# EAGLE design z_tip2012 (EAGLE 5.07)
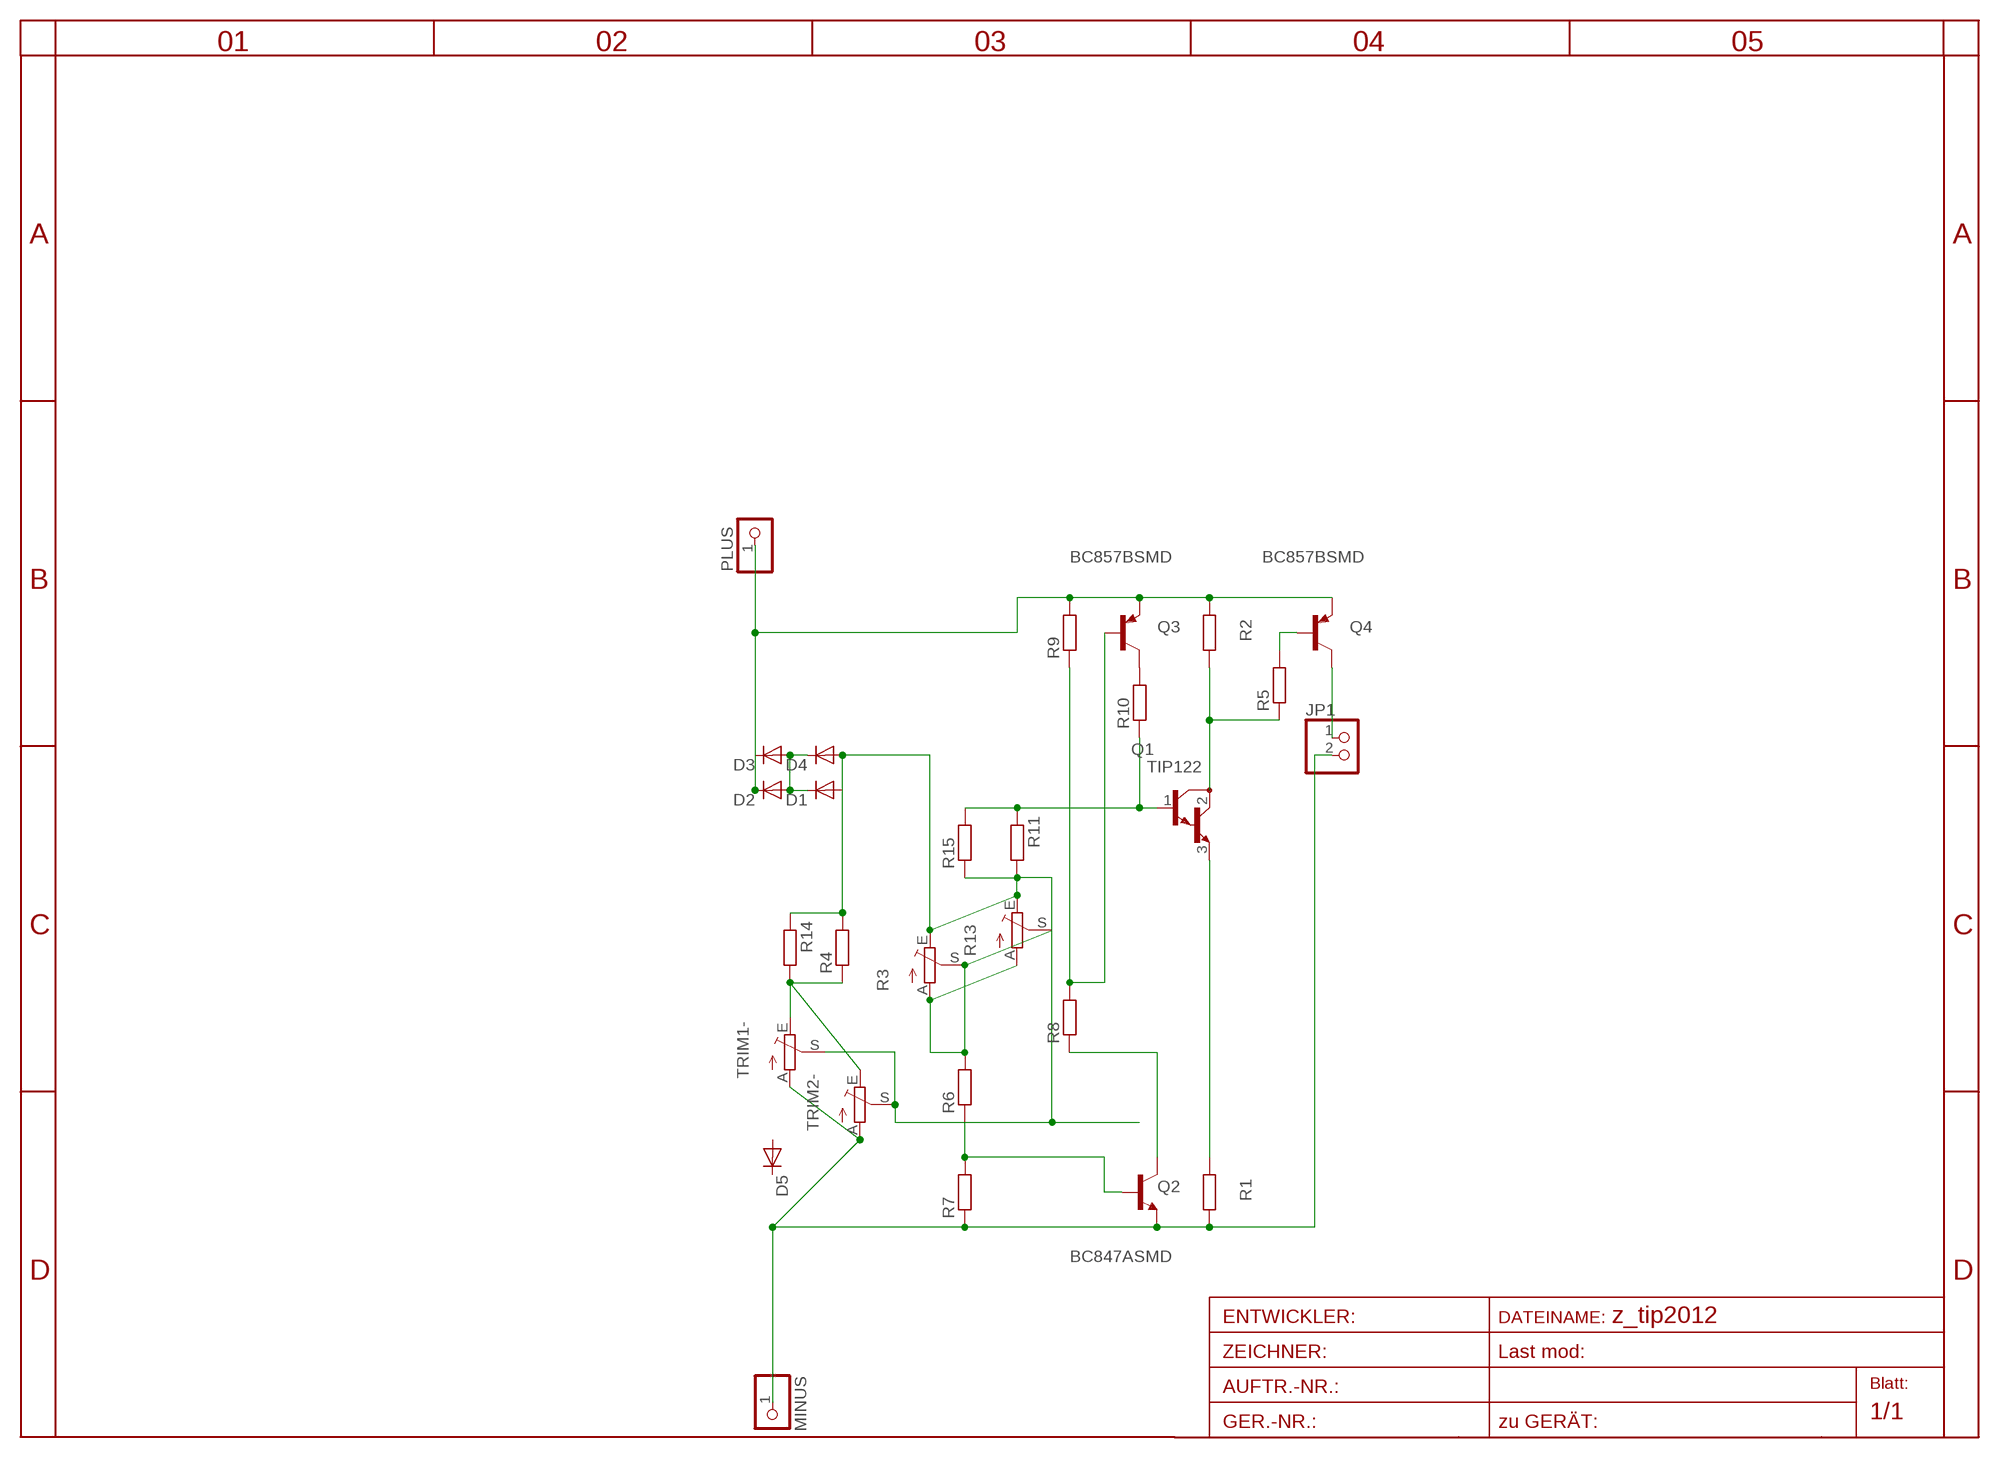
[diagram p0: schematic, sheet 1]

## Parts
D1  DIODE-MINIMELF  [MINIMELF]
D2  DIODE-MINIMELF  [MINIMELF]
D3  DIODE-D-2.5  [D-2.5]
D4  DIODE-D-2.5  [D-2.5]
D5  DIODE-MINIMELF  [MINIMELF]
JP1  PINHD-1X2  [1X02]
MINUS  PINHD-1X11MM6  [1X1MM8]
PLUS  PINHD-1X11MM6  [1X1MM8]
Q1  TIP122  [TO220]
Q2  BC847ASMD  [SOT23]
Q3  BC857BSMD  [SOT23-BEC]
Q4  BC857BSMD  [SOT23-BEC]
R1  R-EU_0411/12  [0411/12]
R2  R-EU_0922V  [0922V]
R3  TRIM_EU-S64W  [S64W]
R4  R-EU_R1206  [R1206]
R5  R-EU_R1206  [R1206]
R6  R-EU_R1206  [R1206]
R7  R-EU_R1206  [R1206]
R8  R-EU_R1206  [R1206]
R9  R-EU_R1206  [R1206]
R10  R-EU_R1206  [R1206]
R11  R-EU_0204/7  [0204/7]
R13  TRIM_EU-EVND_H  [EVND8AA]
R14  R-EU_0204/5  [0204/5]
R15  R-EU_R1206  [R1206]
TRIM1-  TRIM_EU-EVND_H  [EVND8AA]
TRIM2-  TRIM_EU-S64W  [S64W]

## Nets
B: D1.A D4.A R3.E R4.2 R11.2 R13.E R14.1 R15.1 TRIM1-.S TRIM2-.S
C: Q1.2(C) R2.1 R5.1
E: Q1.3(E) R1.2
MINUS: JP1.2 MINUS.1 Q2.2(E) R1.1 R7.1 TRIM1-.A TRIM2-.A
N$1: Q3.C R10.2
N$2: D1.C D2.A D3.A D4.C
N$3: R4.1 R14.2 TRIM1-.E TRIM2-.E
N$4: Q3.B R8.2 R9.1
N$6: Q2.3(C) R8.1
N$7: R3.A R3.S R6.2 R13.A R13.S
N$8: Q2.1(B) R6.1 R7.2
N$9: Q4.B R5.2
N$10: Q1.1(B) R10.1 R11.1 R15.2
N$12: JP1.1 Q4.C
PLUS: D2.C D3.C PLUS.1 Q3.E Q4.E R2.2 R9.2
Unconnected: D5.A D5.C

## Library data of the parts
D1-D5 = diode-1:DIODE-: DIODE
JP1 = pinhead:PINHD-1X2: PIN HEADER
MINUS PLUS = pinhead:PINHD-1X1: PIN HEADER
Q1 = transistor-npn:TIP122*: NPN Darlington Transistor
Q2 = transistor-npn:BC847*: NPN Transistor
Q3 Q4 = transistor-pnp:BC857*: PNP Transistror
R1 R2 R4-R11 R14 R15 = rcl:R-EU_: RESISTOR, European symbol
R3 R13 TRIM1- TRIM2- = pot:TRIM_EU-: POTENTIOMETER

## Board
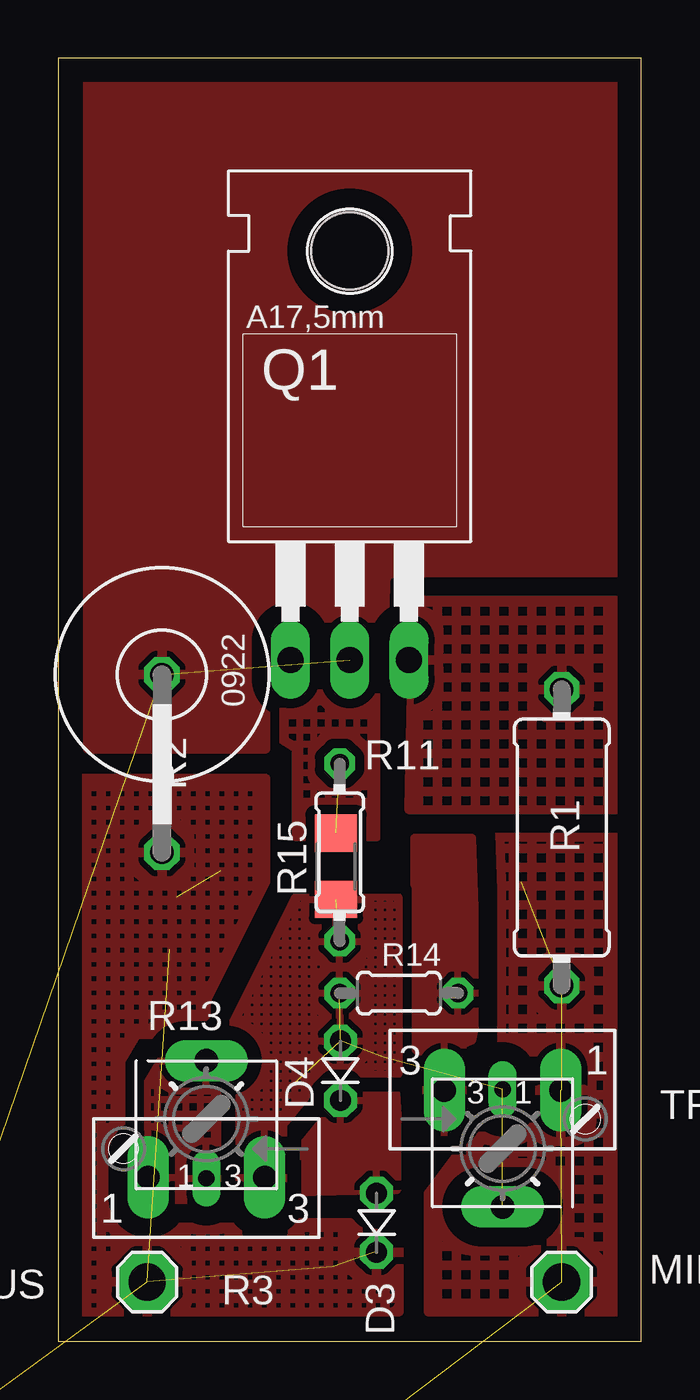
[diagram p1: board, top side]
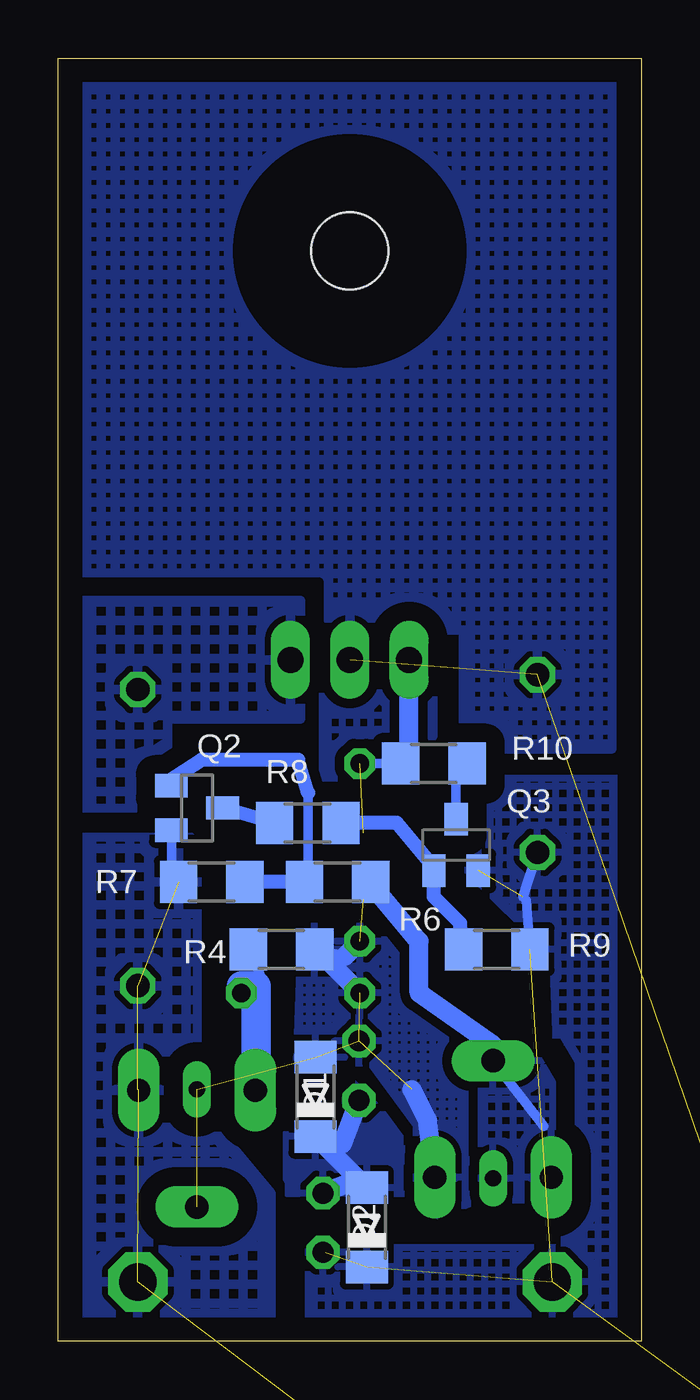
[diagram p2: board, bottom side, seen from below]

Size 25 x 55 mm. Coordinates in mm from the lower left corner, seen from the top.
Outline: 0,0 25,0 25,55 0,55 0,0
Copper layers (1*16): Top 0.035mm / dielectric 1.5mm / Bottom 0.035mm
Design rules "default": minimum track width 10mil, minimum drill 24mil, track to track 8mil, track to pad 8mil, pad to pad 8mil, via to via 8mil, smd to smd 8mil, copper to edge 40mil, drill to drill 8mil, minimum pad ring 10mil, minimum via ring 8mil, stop-mask expansion 4mil, vias tented up to drill 0mil, thermal gap 10mil

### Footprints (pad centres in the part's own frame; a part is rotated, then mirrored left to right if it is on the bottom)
MINIMELF = smd 1.4 x 1.8: A 1.7,0; C -1.7,0
D-2.5 = drill 0.9 octagon: A 1.27,0; C -1.27,0
1X02 = drill 1.016 long: 1 -1.27,0; 2 1.27,0
1X1MM8 = drill 1.6 pad 2.54 octagon: 1 0,0
TO220 = drill 1.118 long: 1 -2.54,-6.35; 2 0,-6.35; 3 2.54,-6.35 | hole 3.302: 0,11.176
SOT23 = smd 1 x 1.4: 1 -0.95,-1.1; 2 0.95,-1.1; 3 0,1.1
SOT23-BEC = smd 1 x 1.4: B -0.95,-1.1; C 0,1.1; E 0.95,-1.1
0411/12 = drill 1 octagon: 1 -6.35,0; 2 6.35,0
0922V = drill 1 octagon: 1 -5.08,0; 2 2.54,0
S64W = drill 0.7 long: A 2.54,1.27; E -2.54,1.27; S 0,1.27
R1206 = smd 1.6 x 1.803: 1 -1.422,0; 2 1.422,0
0204/7 = drill 0.8 octagon: 1 -3.81,0; 2 3.81,0
EVND8AA = drill 1 pad 1.778 long: A -2.5,-2.5; E 2.5,-2.5; S 0,2.5
0204/5 = drill 0.8 octagon: 1 -2.54,0; 2 2.54,0

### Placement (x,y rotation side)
D1  13.97,10.48 90 bottom
D2  11.77,4.88 90 bottom
D3  13.65,5.08 90 top
D4  12.1,11.6 90 top
D5  not placed on the board
JP1  not placed on the board
MINUS  21.59,2.54 0 top
PLUS  3.81,2.54 0 top
Q1  12.5,35.56 0 top
Q2  19.05,22.86 270 bottom
Q3  7.94,21.27 0 bottom
Q4  not placed on the board
R1  21.59,21.59 90 top
R2  4.45,23.5 270 top
R3  6.35,8.26 180 top
R4  15.43,16.8 0 bottom
R5  not placed on the board
R6  13.02,19.68 0 bottom
R7  18.41,19.68 0 bottom
R8  14.3,22.23 0 bottom
R9  6.2,16.8 0 bottom
R10  8.89,24.77 0 bottom
R11  12.06,20.95 270 top
R13  6.35,9.53 0 top
R14  14.61,14.92 0 top
R15  11.91,20.36 90 top
TRIM1-  19.05,8.26 180 top
TRIM2-  19.05,9.53 0 top

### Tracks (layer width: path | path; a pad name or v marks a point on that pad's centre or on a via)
B  (6 unrouted)
  Bottom 0.406: 13.5,16.36 R4.2 12.7,16.51 | R3.E R13.E
  Bottom 0.813: R13.E 9.17,9.48 9.84,10.79 | R14.1 13.5,16.36 | 12.7,16.51 R11.2
  pour Bottom (isolate 0.406, rank 3, hatched): 11.43,17.78 14.6,17.78 14.8,11.93 11.63,11.93 9.66,9.26 9.66,5.45 8.49,5.38 6.35,6.35 6.35,11.43
  pour Top (isolate 0.61, rank 3, hatched): 10.16,19.05 14.6,19.05 14.6,11.43 11.43,11.43 9.66,9.26 9.66,5.45 8.49,5.38 6.35,6.35 6.35,11.43
C  (2 unrouted)
  pour Bottom (isolate 0.813, rank 4, hatched): 24.13,30.48 7.62,30.48 7.62,25.4 1.27,25.4 1.27,54.61 24.13,54.61
  pour Top (isolate 0.813, rank 4): 24.13,30.48 8.89,30.48 8.89,25.4 1.27,25.4 1.27,54.61 24.13,54.61
E
  pour Bottom (isolate 0.813, rank 2, hatched): 14.61,31.75 24.13,31.75 24.13,22.86 21.59,22.86 20.32,24.13 20.32,26.67 14.61,26.67
  pour Top (isolate 0.813, rank 2, hatched): 15.24,31.75 24.13,31.75 23.93,22.79 15.04,22.79
MINUS  (5 unrouted)
  Bottom 0.406: Q2.2 20.15,20 R7.1
  pour Bottom (isolate 0.813, hatched): 19.05,21.59 24.13,21.59 24.13,0 15.88,0 15.88,6.35 19.05,10.16
  pour Top (isolate 0.813, rank 6, hatched): 18.28,21.62 23.93,21.62 24.13,1.27 15.88,1.27 15.88,6.35 17.78,8.89
N$1
  Bottom 0.406: Q3.C 7.94,24.3 R10.2
N$2
  Bottom 0.406: D2.A 12.49,6.78
  Bottom 0.813: D4.C 12.81,8.46 D1.C D2.A | 12.49,6.78 D3.A
  pour Bottom (isolate 0.406, rank 4): 11.43,10.16 12.7,11.43 12.7,10.16 13.97,8.89 15.24,8.89 15.24,6.35 10.16,6.35 10.16,8.89
  pour Top (isolate 0.61, rank 4): 10.16,8.89 12.7,11.43 14.5,10.66 14.57,9.69 14.54,8.99 14.54,6.45 10.16,6.35
N$3
  Bottom 0.406: R4.1 16.34,15.72 R14.2 | 16.55,10.79 TRIM1-.E
  Bottom 1.27: 16.55,10.79 TRIM2-.E 16.51,15.24 17.14,15.24 R14.2
  pour Top (isolate 0.406, rank 4): 15.24,21.59 15.2,12.6 15.74,12.06 15.74,8.99 17.38,8.89 17.38,12.7 17.78,12.88 17.9,13.4 17.9,18.53 17.78,21.59
N$4
  Bottom 0.406: Q3.B 8.89,20.32
  Bottom 0.61: R9.1 7.77,17.93 8.89,19.05 Q3.B | 8.89,20.32 10.48,22.23 R8.2
N$5
  pour Bottom (isolate 0.406, rank 5, hatched): 8.89,29.21 8.9,25.9 9.5,25.8 10.16,25.4 10.16,24.13 13.67,24.13 13.67,27.94
  pour Top (isolate 0.406, rank 5, hatched): 8.89,29.21 8.9,25.9 9.5,25.8 10.16,25.4 10.16,21.59 13.67,21.59 13.67,27.94
N$6
  Bottom 0.61: R8.1 Q2.3
N$7
  Bottom 0.406: 4.17,9.21 R13.S 6.35,12.7 | 11.28,19.21 R6.2
  Bottom 0.813: 11.28,19.21 9.53,17.14 9.53,14.92 6.35,12.7
  pour Bottom (isolate 0.305, hatched): 6.85,12.7 4.76,12.7 3.81,11.11 3.81,6.35 4.45,6.03 6.85,6.03
  pour Top (isolate 0.305, hatched): 6.85,12.7 4.76,12.7 3.81,11.11 3.81,6.35 4.45,6.03 6.85,6.03
N$8
  Bottom 0.406: R6.1 14.29,20.32 14.29,23.51 | 20.32,23.98 Q2.1
  Bottom 0.61: 14.29,23.51 14.72,24.93 18.86,24.93 20.32,23.98 | R6.1 R7.2
N$9  (1 unrouted)
N$10  (1 unrouted)
  Bottom 0.406: 9.96,25.12 R10.1 R11.1
  Bottom 0.813: 9.96,25.12 Q1.1
N$12  (1 unrouted)
PLUS  (5 unrouted)
  Bottom 0.406: D3.C 13.54,3.81 | R9.2 4.93,18.9 5.08,19.05 R2.2
  pour Bottom (isolate 0.813, rank 2, hatched): 0,24.13 7.62,24.13 7.62,20.32 3.81,16.51 3.31,4 14.29,4 14.29,0 0,0
  pour Top (isolate 0.813, rank 6, hatched): 0,24.13 8.89,24.13 8.89,16.51 3.81,11.43 3.81,5.08 13.97,5.08 14.61,4.45 14.61,1.27 0,1.27

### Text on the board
tTest: fuse | 1R8 10W | 101 | 202 | minus | plus | C..A
bTest: TIP122 | fuse | 1R8 10W | 101 | 202 | minus | plus | C..A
